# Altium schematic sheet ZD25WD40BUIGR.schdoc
size 127 x 101 mm
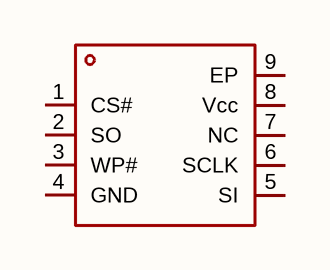
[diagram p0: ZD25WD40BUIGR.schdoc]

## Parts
U?  zd25wd40buigr  [USON-8_L3.0-W2.0-P0.50-BL-EP_ZD25XX]  (value not drawn)

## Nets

Not connected (* = marked no-connect by the designer): U? 1(CS#) 2(SO) 3(WP#) 4(GND) 5(SI) 6(SCLK) 7(NC) 8(Vcc) 9(EP)

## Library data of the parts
U? = zd25wd40buigr: 接口类型:SPI;存储容量:4Mbit;时钟频率(fc):85MHz;; Manufacturer: Zetta(澜智); AddInBom: yes; ModelId: 12a239e5c7384371915ecb51201bf581; ModelName: USON-8_L3.0-W2.0-H0.6-P0.50; ModelTransform: 118.8974,78.74,0,90,0,0,0,0,0; Interface: SPI; Memory Size: 4Mbit; Clock Frequency: 85MHz; Voltage - Supply: 1.65V~2V; Standby Supply Current: 9uA; Program / Erase Cycles: 100000次; Page Programming Time (Tpp): 1.3ms; Block Erase Time(tBE): 10ms@(32KB); Data Retention - TDR (Year): 20年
